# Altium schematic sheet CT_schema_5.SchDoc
size 283 x 147 mm
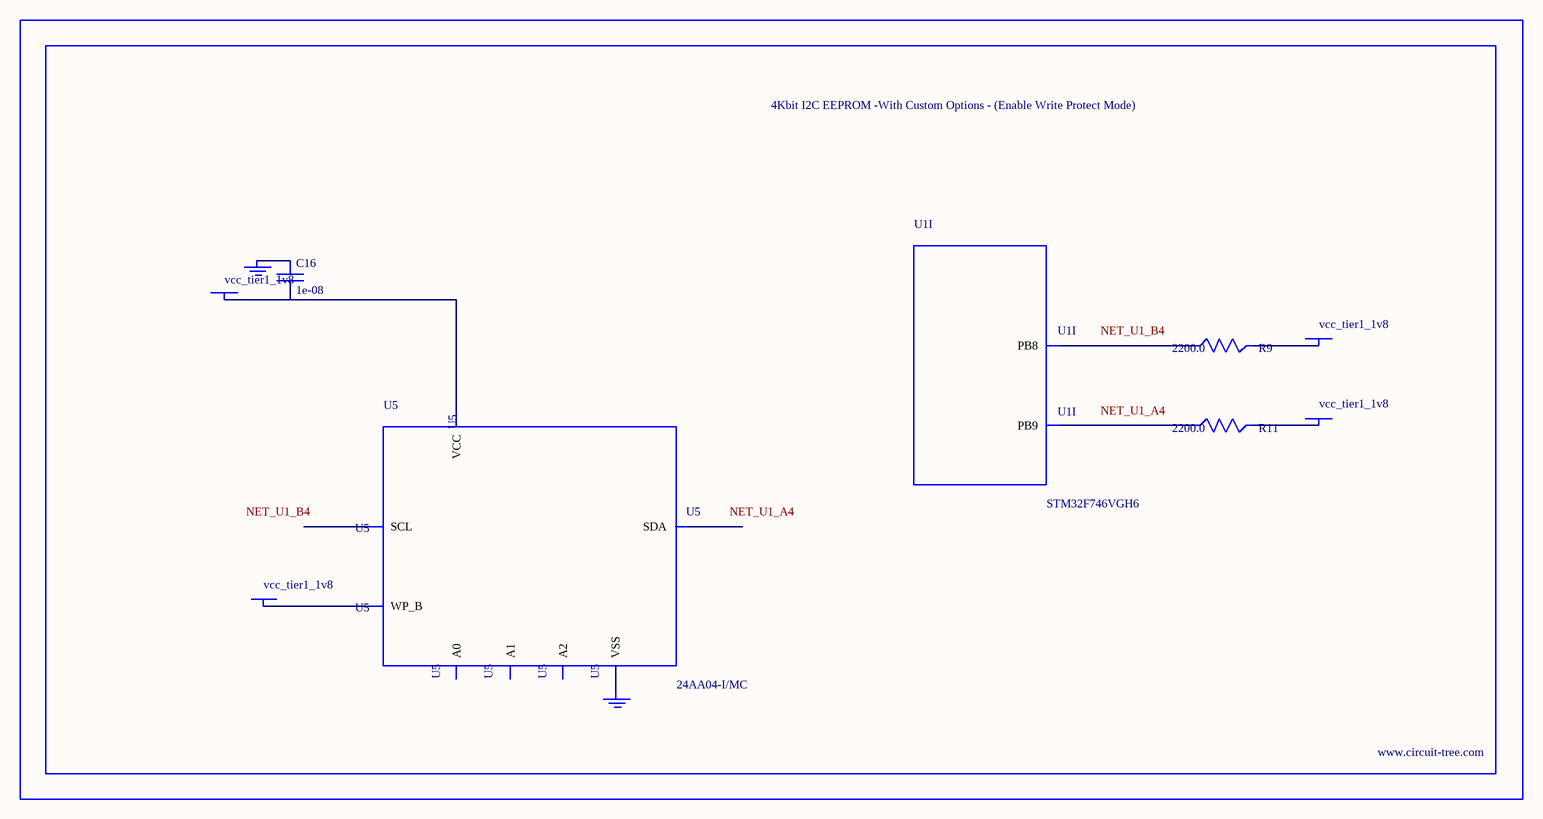
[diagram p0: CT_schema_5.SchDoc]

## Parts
BORDER4  (no value)
C16  1e-08  [C0402]
GND_INSTANCE_4_0  (no value)
GND_INSTANCE_4_1  (no value)
POWER_INSTANCE_4_0  vcc_tier1_1v8
POWER_INSTANCE_4_1  vcc_tier1_1v8
POWER_INSTANCE_4_2  vcc_tier1_1v8
POWER_INSTANCE_4_3  vcc_tier1_1v8
R9  2200.0  [R0603]
R11  2200.0  [R0603]
U1  STM32F746VGH6  [TFBGA100]  (part I of 10)
U5  24AA04-I/MC  [TDFN-8/6MM]

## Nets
NetC16_1: C16.1 GND_INSTANCE_4_0.0(GND)
NetC16_2: C16.2 POWER_INSTANCE_4_1.0(PWR) U5.8(VCC)
NetGND_INSTANCE_4_1_0: GND_INSTANCE_4_1.0(GND) U5.4(VSS)
NetPOWER_INSTANCE_4_0_0: POWER_INSTANCE_4_0.0(PWR) U5.7(WP_B)
NetPOWER_INSTANCE_4_2_0: POWER_INSTANCE_4_2.0(PWR) R9.2
NetPOWER_INSTANCE_4_3_0: POWER_INSTANCE_4_3.0(PWR) R11.2
NetR9_1: R9.1 U1.B4(PB8)
NetR11_1: R11.1 U1.A4(PB9)

Not connected (* = marked no-connect by the designer): U5 1(A0) 2(A1) 3(A2) 5(SDA) 6(SCL)

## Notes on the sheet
- Labels drawn without touching a wire or pin: NET_U1_A4, NET_U1_B4

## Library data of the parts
BORDER4 = BORDER_PAGE4
C16 = C0402C103K3RAC
GND_INSTANCE_4_0 GND_INSTANCE_4_1 = GND
POWER_INSTANCE_4_0-POWER_INSTANCE_4_3 = PWR
R9 R11 = RC0603JR-072K2L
